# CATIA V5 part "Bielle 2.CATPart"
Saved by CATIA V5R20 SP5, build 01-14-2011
Part number: Bielle 2
Bounding box of the stored display mesh (mm): x -110 to -90, y -260 to -40, z -25 to 25
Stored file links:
  U:\CFAO\Thinkmotion\Bielle 2.CATPart
  U:\CFAO\Thinkmotion\Bras Articule.CATProduct
  U:\CFAO\Thinkmotion\Squelette Bielle 2.CATPart
  U:\CFAO\Thinkmotion\Part1.CATPart
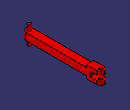
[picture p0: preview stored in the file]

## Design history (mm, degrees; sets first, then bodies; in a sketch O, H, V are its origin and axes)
Set1
  Plane1: linked copy from another document
  DatumCurve1 to DatumCurve3: linked copy from another document
  Line1: linked copy from another document
  Point1: linked copy from another document
  Line2: linked copy from another document
  Plane2: linked copy from another document
Body1 (main body)
  Sketch1 on Plane1, origin (-100, 0, 0), H (0, 1, 0), V (0, 0, 1)
    line L1 (-40, 17) -> (-80, 17)
    line L2 (-80, 17) -> (-80, 10)
    line L3 (-80, 10) -> (-260, 10)
    line L4 (-260, 10) -> (-260, -10)
    line L5 (-260, -10) -> (-80, -10)
    point P6 (-80, -10)
    line L6 (-80, -10) -> (-80, -17)
    line L7 (-80, -17) -> (-40, -17)
    line L8 (-40, -17) -> (-40, -7)
    line L9 (-40, -7) -> (-70, -7)
    line L10 (-70, -7) -> (-70, 7)
    line L11 (-70, 7) -> (-40, 7)
    line L12 (-40, 17) -> (-40, 7)
    reference projected line E1 (0, -5) -> (-50, -5) from edge of DatumCurve1
    reference projected line E2 (0, 5) -> (-50, 5) from edge of DatumCurve2
    reference projected line E3 (-60, 5) -> (-60, -5) from edge of DatumCurve3
    reference projected line E4 (-50, 0) -> (-250, 0) from Line1
    reference projected line E5 (-50, 0) -> (-250, 0) from Line1
    reference projected point E6 (-250, 0) from Point1
    reference projected line E7 (-50, -30) -> (-50, 30) from Line2
    length L12 = 10
    length L8 = 10
    distance L9 E1 = 2
    distance L11 E2 = 2
    distance L10 E3 = 10
    distance E5 L5 = 10
    distance L10 L6 = 10
    distance L4 E6 = 10
    distance L12 E7 = 10
    horizontal: L1 H, L3 H, L5 H, L7 H, L9 H, L11 H
    vertical: L2 V, L4 V, L6 V, L8 V, L10 V, L12 V
    coincidence: P6 L2, L8 L12
    symmetry: L3 L5 E4
  Pad1: profile Sketch1, direction (1, 0, 0), length 10, mirrored extent
  Fillet1: radius 10, on edge [start face of Pad1 | face of Pad1 from Sketch1.L8]; edge [face of Pad1 from Sketch1.L8 | end face of Pad1]; edge [start face of Pad1 | face of Pad1 from Sketch1.L12]; edge [face of Pad1 from Sketch1.L12 | end face of Pad1]; edge [face of Pad1 from Sketch1.L4 | end face of Pad1]; edge [start face of Pad1 | face of Pad1 from Sketch1.L4]
  Sketch2 on face of Pad1 from Sketch1.L1, origin (0, 0, 17), H (1, 0, 0), V (0, 1, 0)
    circle A1 centre (-100, -50) radius 5
    reference projected arc E1 centre (-100, -50) radius 10 from (-90, -50) to (-100, -40) ccw from edge [face of Pad1 from Sketch1.L1 | face of Fillet1]
    radius A1 = 5
    concentricity: A1 E1
  Pocket1: profile Sketch2, direction (0, 0, -1), through (limit type 3)
  Sketch3 on Plane2, origin (0, 0, 0), H (1, 0, 0), V (0, 1, 0)
    circle A1 centre (-100, -250) radius 5
    reference projected arc E1 centre (-100, -250) radius 10 from (-110, -250) to (-100, -260) ccw from edge [face of Pad1 from Sketch1.L3 | face of Fillet1]
    radius A1 = 5
    concentricity: A1 E1
  Pad2: profile Sketch3, direction (0, 0, 1), length 25, mirrored extent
